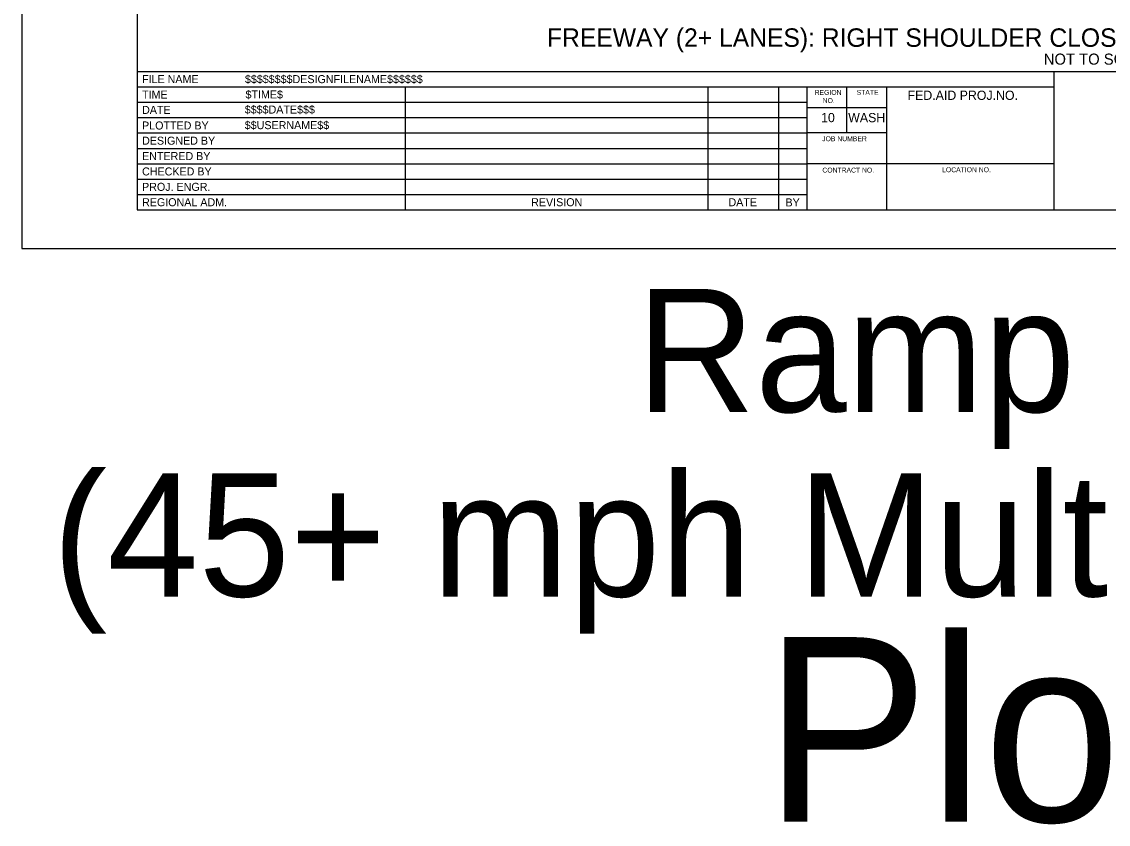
# Model space of a CAD drawing. Extents: x 99999.1 to 100055.7, y 99995 to 100013.2.
# Drawn here: x 100019.06 to 100027.9, y 99995.01 to 100001.53 of the extents above; entities that cross this region are included whole.
import ezdxf

# ---------------------------------------------------------------- set-up
doc = ezdxf.new("R2010")
doc.units = 0
for name, color, linetype in [('SH_DE_DetailHeading1Text', 7, 'Continuous'), ('SH_GI_PlotLimits', 7, 'Continuous'), ('SH_GI_SheetBorder', 7, 'Continuous'), ('SH_GI_SheetLocationText', 7, 'Continuous'), ('SH_GI_SheetTextInCells', 7, 'Continuous'), ('SH_GI_TitleBlockText', 7, 'Continuous')]:
    doc.layers.add(name, color=color, linetype=linetype)

msp = doc.modelspace()

# ---------------------------------------------------------------- linework, layer by layer
at = {"layer": 'SH_GI_PlotLimits'}
msp.add_lwpolyline([(100019.0625, 99999.6875), (100036.0625, 99999.6875), (100036.0625, 100010.6875), (100019.0625, 100010.6875)], close=True, dxfattribs=at)
at = {"layer": 'SH_GI_SheetBorder'}
for p, q in [((100020, 100010.375), (100020, 100000)), ((100020, 100001.1259), (100035.75, 100001.1259)), ((100027.4566, 100000), (100027.4566, 100001.1259)), ((100020, 100001.0008), (100027.4566, 100001.0008)), ((100022.179, 100001.0008), (100022.179, 100000)), ((100024.641, 100001.0008), (100024.641, 100000)), ((100025.2164, 100001.0008), (100025.2164, 100000)), ((100025.4451, 100001.0008), (100025.4451, 100000)), ((100025.7719, 100000.6255), (100025.7719, 100001.0008)), ((100026.0956, 100000), (100026.0956, 100001.0008)), ((100020, 100000.8757), (100022.1821, 100000.8757)), ((100022.1821, 100000.8757), (100025.4466, 100000.8757)), ((100020, 100000.7506), (100022.1821, 100000.7506)), ((100022.1821, 100000.7506), (100025.4466, 100000.7506)), ((100026.0958, 100000.831), (100025.4466, 100000.831)), ((100020, 100000.6255), (100025.4466, 100000.6255)), ((100026.0958, 100000.6255), (100025.4466, 100000.6255)), ((100020, 100000.5004), (100025.4466, 100000.5004)), ((100020, 100000.3753), (100025.4466, 100000.3753)), ((100027.4566, 100000.3753), (100025.4466, 100000.3753)), ((100020, 100000.2502), (100025.4466, 100000.2502)), ((100020, 100000.1251), (100025.4466, 100000.1251)), ((100020, 100000), (100035.75, 100000))]:
    msp.add_line(p, q, dxfattribs=at)

# ---------------------------------------------------------------- texts
at = {"layer": 'SH_DE_DetailHeading1Text'}
for s, height, p in [('FREEWAY (2+ LANES): RIGHT SHOULDER CLOSURE (MAINTAIN EXISTING SPEED LIMIT)', 0.15, (100023.3333, 100001.3259)), ('NOT TO SCALE', 0.09, (100027.3727, 100001.1809))]:
    msp.add_text(s, height=height, rotation=360, dxfattribs=at).set_placement(p)
at = {"layer": 'SH_GI_SheetLocationText'}
for s, height, p in [('Ramp Details', 1, (100024.0609, 99998.3571)), ('(45+ mph Multi lane Highways)', 1, (100019.3114, 99996.8571)), ('Plot 2', 1.5, (100025.0998, 99995.0267))]:
    msp.add_text(s, height=height, dxfattribs=at).set_placement(p)
at = {"layer": 'SH_GI_SheetTextInCells'}
for s, height, p in [('FILE NAME', 0.06505, (100020.041, 100001.0308)), ('TIME', 0.06505, (100020.041, 100000.9057)), ('REGION', 0.04003, (100025.5099, 100000.9352)), ('STATE', 0.04003, (100025.8511, 100000.9357)), ('FED.AID PROJ.NO.', 0.07506, (100026.2652, 100000.8945)), ('DATE', 0.06505, (100020.041, 100000.7806)), ('NO.', 0.04003, (100025.5752, 100000.869)), ('10', 0.07506, (100025.5621, 100000.7131)), ('WASH', 0.07506, (100025.7826, 100000.7131)), ('PLOTTED BY', 0.06505, (100020.041, 100000.6538)), ('DESIGNED BY', 0.065052, (100020.041, 100000.5304)), ('JOB NUMBER', 0.04003, (100025.5712, 100000.5587)), ('ENTERED BY', 0.06505, (100020.041, 100000.4053)), ('CHECKED BY', 0.06505, (100020.041, 100000.2802)), ('CONTRACT NO.', 0.040032, (100025.5725, 100000.3037)), ('LOCATION NO.', 0.040032, (100026.5465, 100000.3067)), ('PROJ. ENGR.', 0.065052, (100020.041, 100000.1551)), ('REGIONAL ADM.', 0.065052, (100020.041, 100000.03)), ('REVISION', 0.06505, (100023.2048, 100000.03)), ('DATE', 0.06505, (100024.8091, 100000.03)), ('BY', 0.06505, (100025.2725, 100000.0285))]:
    msp.add_text(s, height=height, dxfattribs=at).set_placement(p)
at = {"layer": 'SH_GI_TitleBlockText'}
for s, height, p in [('$$$$$$$$DESIGNFILENAME$$$$$$', 0.065052, (100020.8775, 100001.0308)), ('$TIME$', 0.06505, (100020.882, 100000.9059)), ('$$$$DATE$$$', 0.065052, (100020.8759, 100000.7835)), ('$$USERNAME$$', 0.065052, (100020.8759, 100000.6567))]:
    msp.add_text(s, height=height, dxfattribs=at).set_placement(p)

doc.saveas('drawing.dxf')
